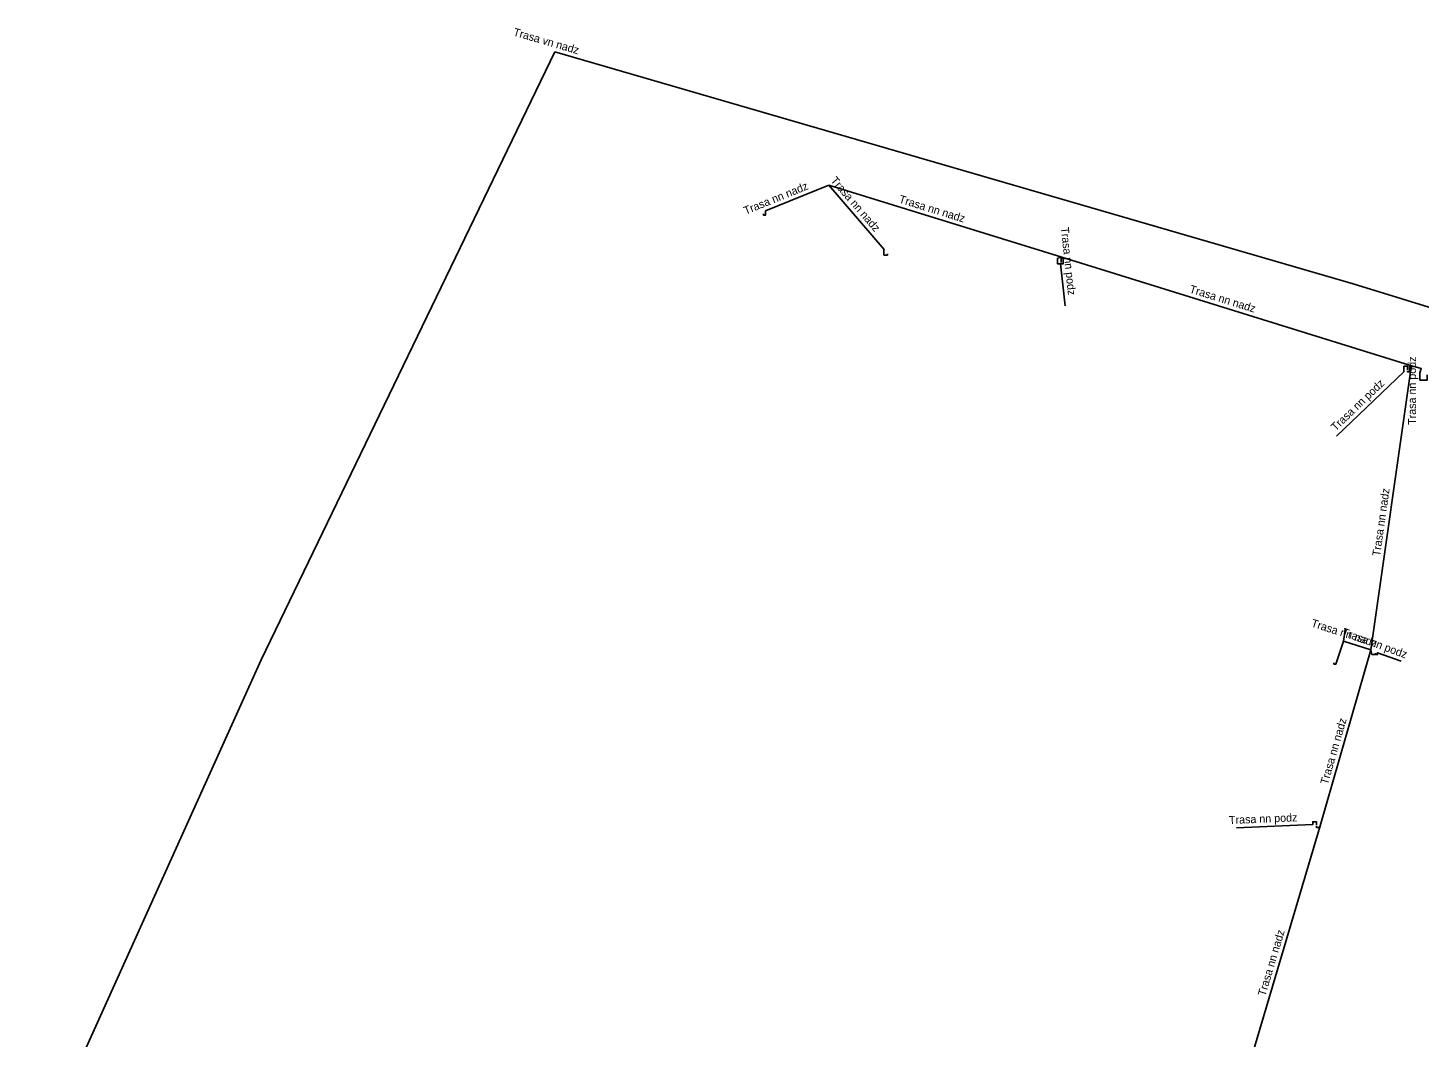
# Model space of a CAD drawing. Extents: x -742082 to -717476, y -1040737 to -1024597.
# Drawn here: x -736000.4 to -735826.6, y -1031771.9 to -1031645.8 of the extents above; entities that cross this region are included whole.
import ezdxf

# ---------------------------------------------------------------- set-up
doc = ezdxf.new("R2010")
doc.units = 0
for name, color, linetype in [('Level 13', 7, 'Continuous'), ('Level 14', 7, 'Continuous'), ('Level 15', 7, 'Continuous'), ('Level 20', 7, 'Continuous'), ('Level 24', 7, 'Continuous')]:
    doc.layers.add(name, color=color, linetype=linetype)

msp = doc.modelspace()

# ---------------------------------------------------------------- linework, layer by layer
at = {"layer": 'Level 13'}
for p, q in [((-735832.59, -1031723.49), (-735838.91, -1031745.46)), ((-735838.91, -1031745.46), (-735848.11, -1031776.38))]:
    msp.add_line(p, q, dxfattribs=at)
for points in [[(-735871.3, -1031675.1), (-735871.3, -1031675.26), (-735871.75, -1031675.26), (-735871.75, -1031674.55), (-735871.22, -1031674.41)], [(-735828, -1031688.6), (-735828, -1031688.76), (-735827.74, -1031688.76), (-735827.74, -1031688.21), (-735827.76, -1031687.92)], [(-735835.8, -1031720.8), (-735835.8, -1031720.96), (-735836, -1031722.4)], [(-735837.2, -1031725.1), (-735837.2, -1031725.26), (-735836.95, -1031725.26), (-735836, -1031722.4)], [(-735832, -1031723.9), (-735832, -1031724.07), (-735832.45, -1031724.07), (-735832.59, -1031723.49)], [(-735839.4, -1031745.5), (-735839.4, -1031745.66), (-735839.15, -1031745.66), (-735838.91, -1031745.46)]]:
    msp.add_lwpolyline(points, dxfattribs=at)
at = {"layer": 'Level 14'}
for p, q in [((-735871.22, -1031674.41), (-735900.35, -1031665.43)), ((-735827.76, -1031687.92), (-735871.22, -1031674.41)), ((-735832.59, -1031723.49), (-735836, -1031722.4))]:
    msp.add_line(p, q, dxfattribs=at)
for points in [[(-735900.35, -1031665.43), (-735908.24, -1031668.65), (-735908.24, -1031669.16), (-735908.5, -1031669.16), (-735908.5, -1031669)], [(-735900.35, -1031665.43), (-735893.4, -1031673.45), (-735893.45, -1031673.45), (-735893.45, -1031674.16), (-735893, -1031674.16), (-735893, -1031674)], [(-735827.76, -1031687.92), (-735827.57, -1031688.17), (-735832.59, -1031723.49)]]:
    msp.add_lwpolyline(points, dxfattribs=at)
at = {"layer": 'Level 15'}
for points in [[(-735871.3, -1031674.99), (-735871.3, -1031674.55), (-735871.05, -1031674.55), (-735871.05, -1031675.26), (-735871.36, -1031675.26), (-735870.8, -1031680.5)], [(-735828, -1031688.49), (-735828, -1031688.05), (-735828.45, -1031688.05), (-735828.45, -1031688.73), (-735836.9, -1031696.8)], [(-735825.54, -1031689.11), (-735825.54, -1031689.78), (-735826.45, -1031689.78), (-735826.45, -1031688.88), (-735826.3, -1031688.33), (-735827.76, -1031687.92)], [(-735832, -1031723.9), (-735831.93, -1031724.07), (-735831.74, -1031724.07), (-735831.74, -1031723.83), (-735828.8, -1031724.9)], [(-735839.4, -1031745.39), (-735839.4, -1031744.95), (-735839.85, -1031744.95), (-735839.85, -1031745.31), (-735849.4, -1031745.7)]]:
    msp.add_lwpolyline(points, dxfattribs=at)
at = {"layer": 'Level 24'}
msp.add_lwpolyline([(-735784.52, -1031693.24), (-735834.82, -1031677.73), (-735934.57, -1031648.78), (-735971.29, -1031724.72), (-736000.44, -1031789.31)], dxfattribs=at)

# ---------------------------------------------------------------- texts
at = {"layer": 'Level 20'}
for s, rotation, p in [('Trasa vn nadz', 343.8155, (-735939.85, -1031646.72)), ('Trasa nn nadz', 22.2191, (-735910.73, -1031669.13)), ('Trasa nn nadz', 310.8987, (-735900.17, -1031664.88)), ('Trasa nn nadz', 342.8669, (-735891.65, -1031667.59)), ('Trasa nn podz', 276.1158, (-735871.34, -1031670.72)), ('Trasa nn nadz', 342.7299, (-735855.34, -1031678.82)), ('Trasa nn podz', 90, (-735826.95, -1031695.37)), ('Trasa nn podz', 43.6679, (-735837, -1031696.2)), ('Trasa nn nadz', 81.9189, (-735831.44, -1031711.83)), ('Trasa nn nadz', 342.2736, (-735840.13, -1031720.55)), ('Trasa nn podz', 340.017, (-735836.29, -1031721.64)), ('Trasa nn nadz', 73.9513, (-735837.97, -1031740.38)), ('Trasa nn podz', 2.3138, (-735850.3, -1031745.24)), ('Trasa nn nadz', 73.43, (-735845.78, -1031766.8))]:
    msp.add_text(s, height=1, rotation=rotation, dxfattribs=at).set_placement(p)

doc.saveas('drawing.dxf')
